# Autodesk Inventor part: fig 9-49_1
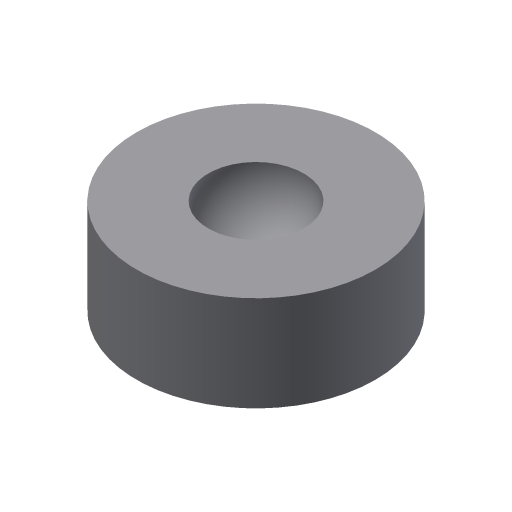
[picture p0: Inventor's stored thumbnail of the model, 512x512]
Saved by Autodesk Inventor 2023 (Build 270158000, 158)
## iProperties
Created: 2013-03
Part Number: fig 9-49_1
Material: Generic
Document SubType Name: Modeling
Designer: CADCIM
Density: 1 g/cm^3
Appearance: Default
Author: CADCIM
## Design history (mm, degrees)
sketch "Sketch1"
  geometry: C1 r 12.5 at (0, 0); 1 further point
  constraints: 1 centre point, 1 coincident
  dimensions: "d0" = 25 diameter of C1
extrude "Extrusion1" new body sketch "Sketch1" distance "d2" = 10; taper "d3" = 0 deg
sketch "Sketch2"
  geometry: L1 (12.5, 10)-(-12.5, 10) reference; L2 (-5, 10)-(5, 10); A1 r 5 centre (0, 10) between (-5, 10) and (5, 10); 1 further point
  constraints: 2 end point, 2 point on circle, 2 point on line, 1 centre point, 1 midpoint
  dimensions: "d4" = 10 diameter of A1
revolve "Revolution1" sketch "Sketch2" stored, may be unused: angle "d6" = 90 deg
body "Solid1"
